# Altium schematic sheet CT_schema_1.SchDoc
size 808 x 528 mm
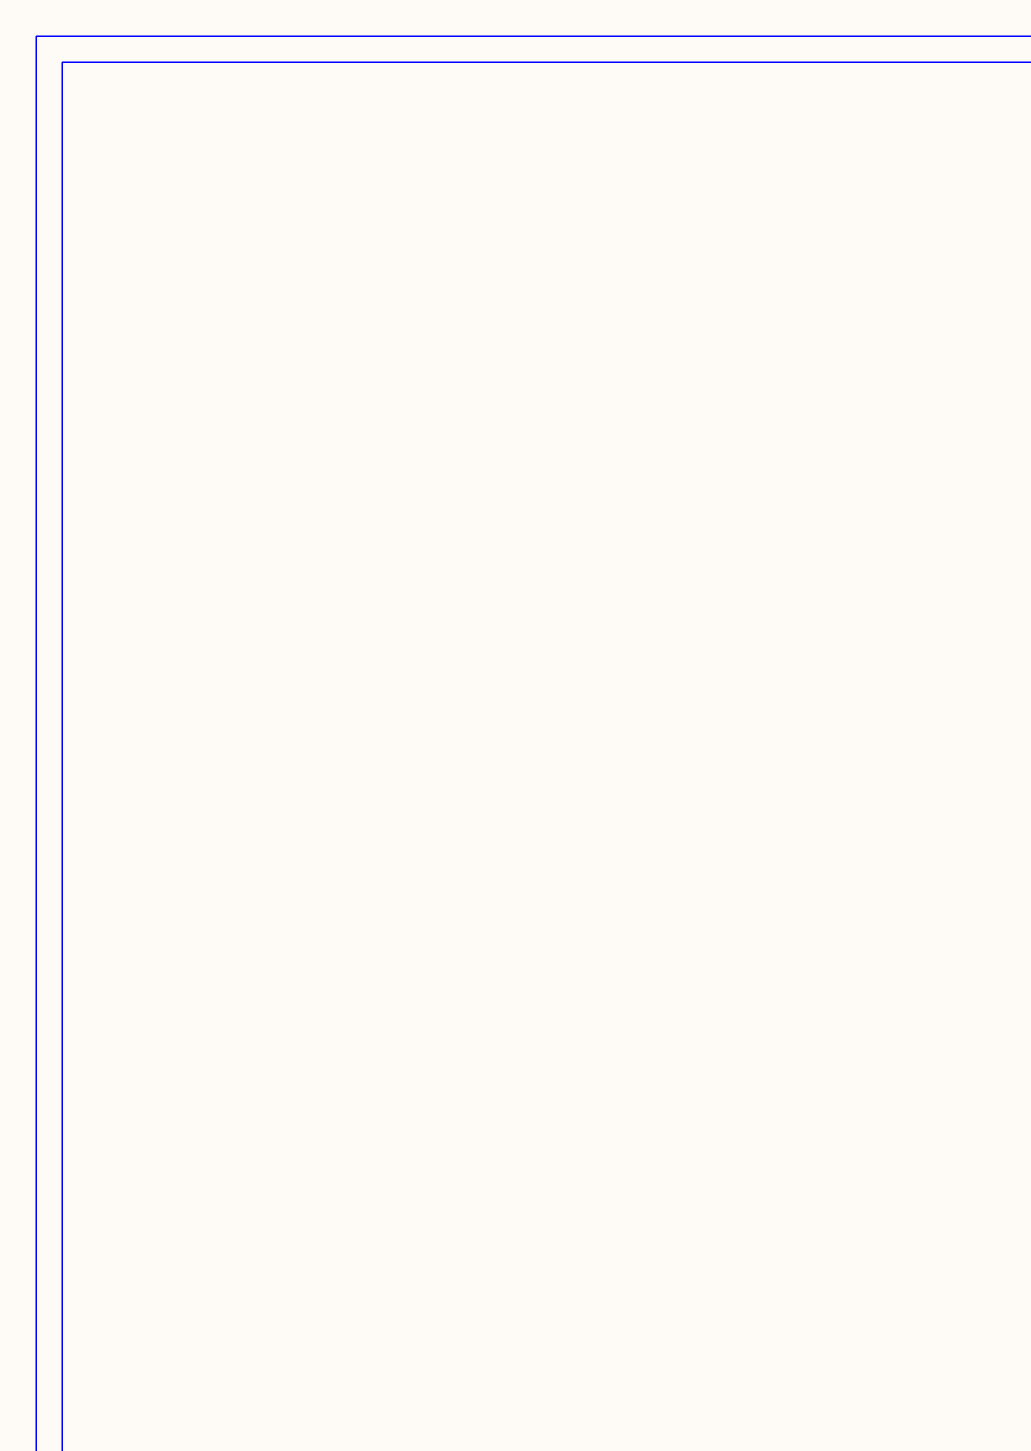
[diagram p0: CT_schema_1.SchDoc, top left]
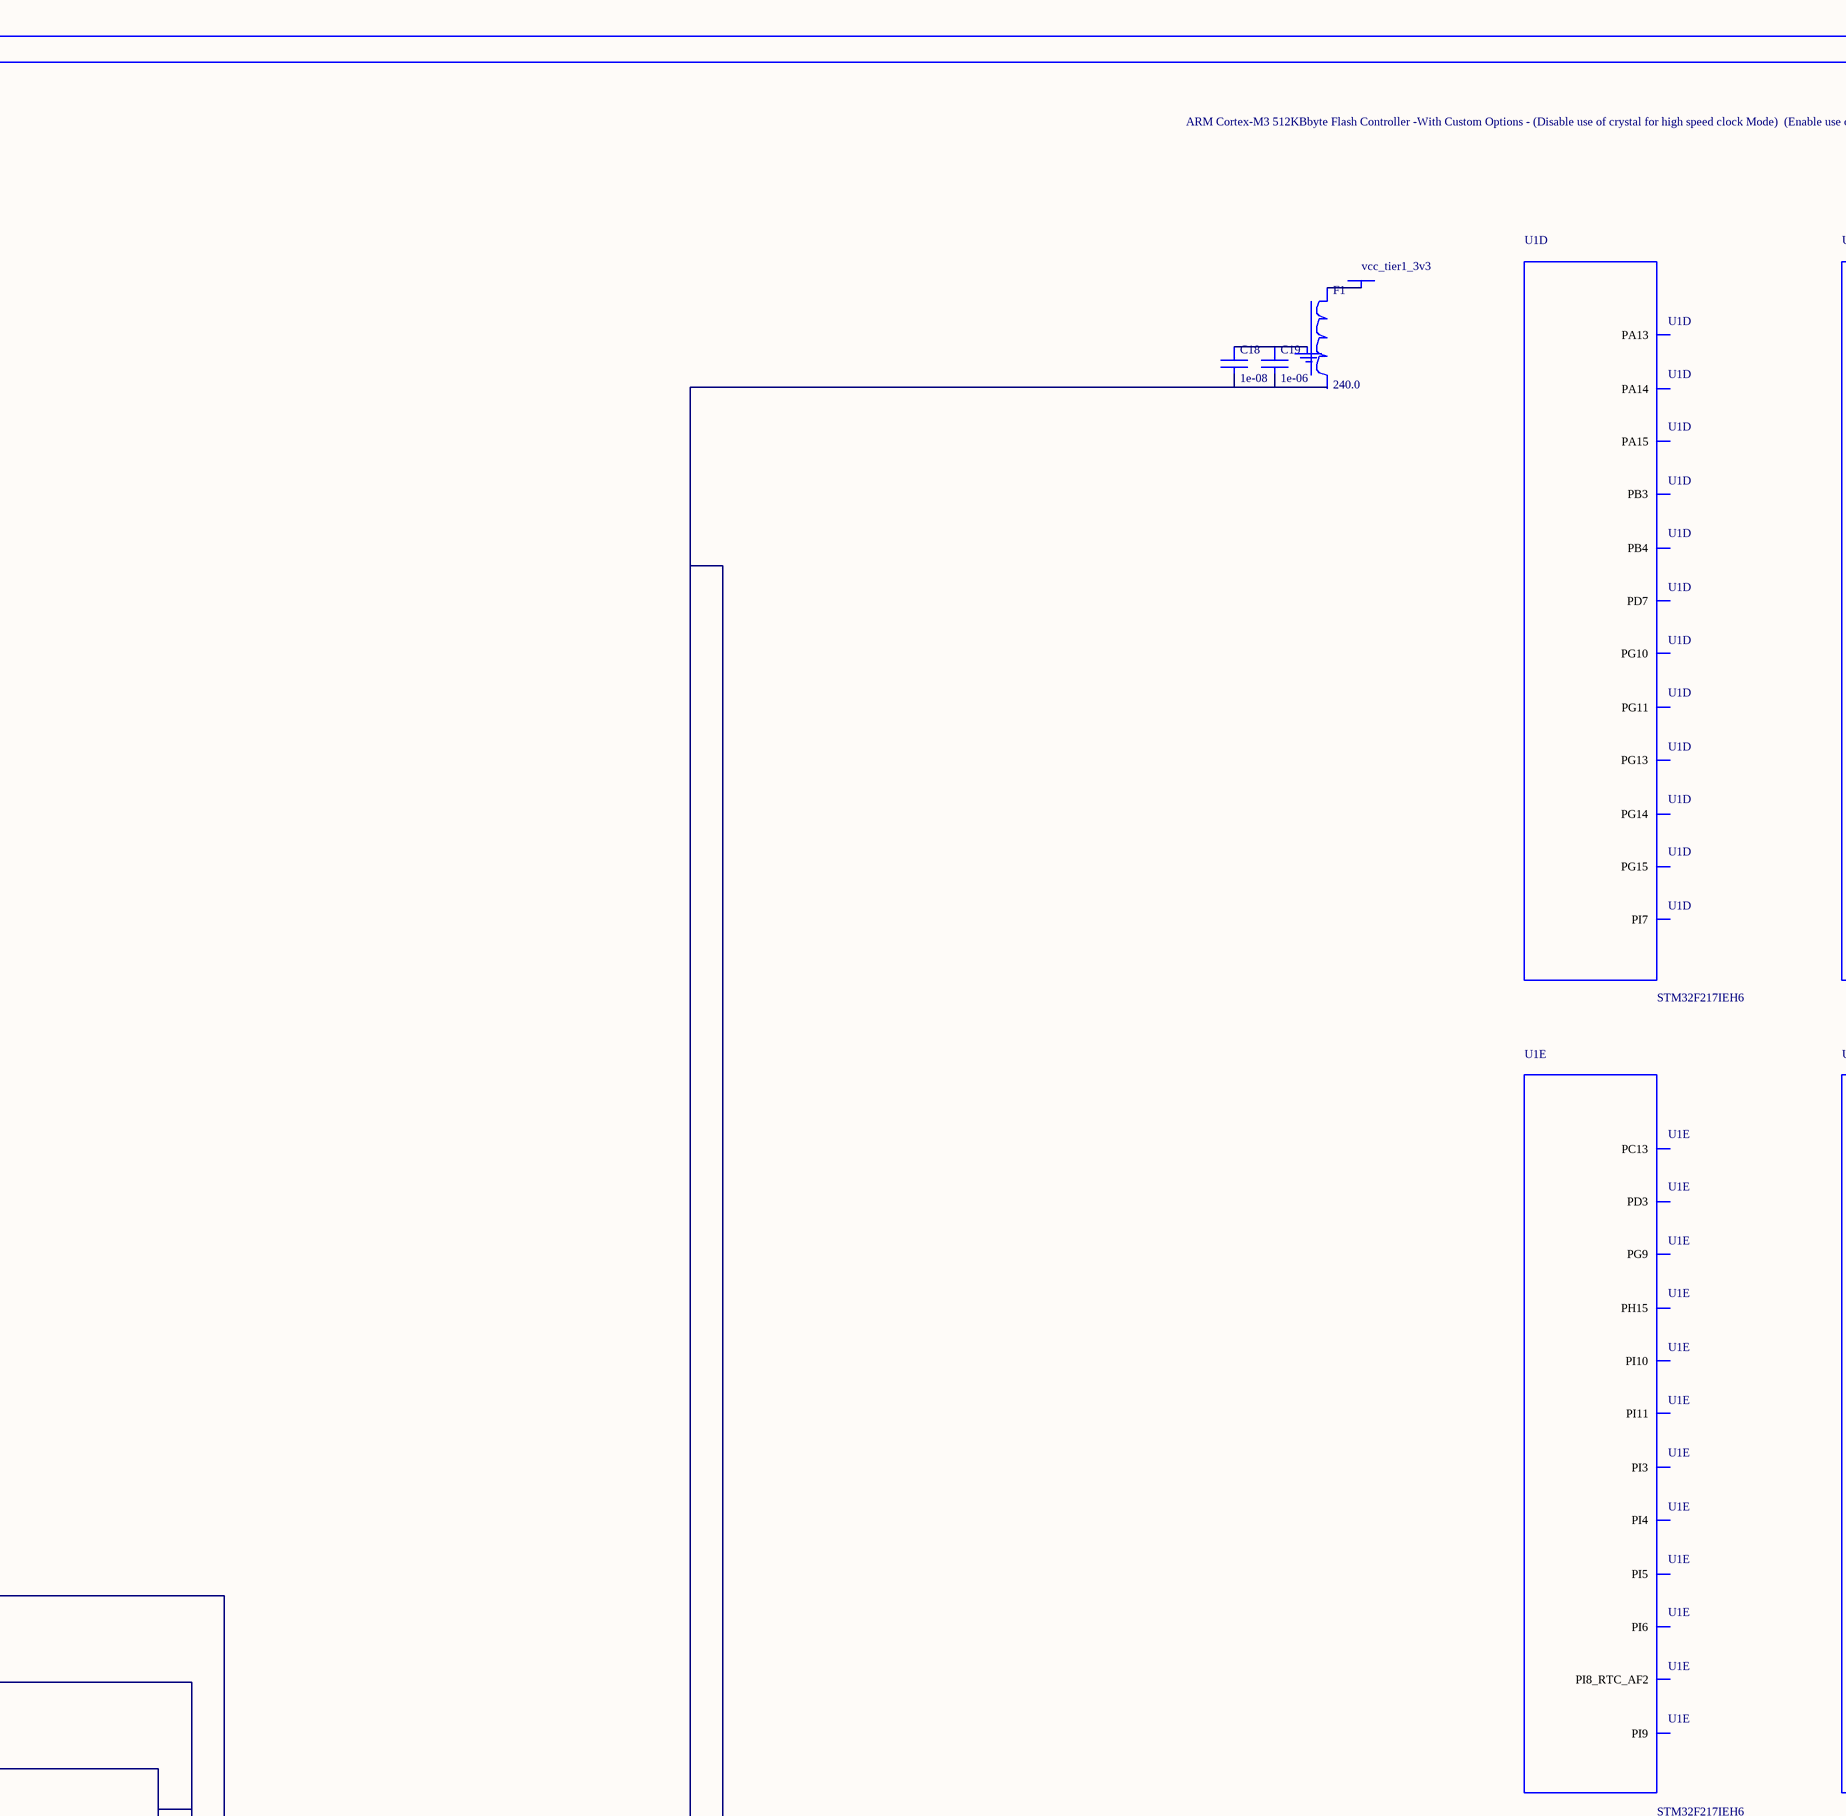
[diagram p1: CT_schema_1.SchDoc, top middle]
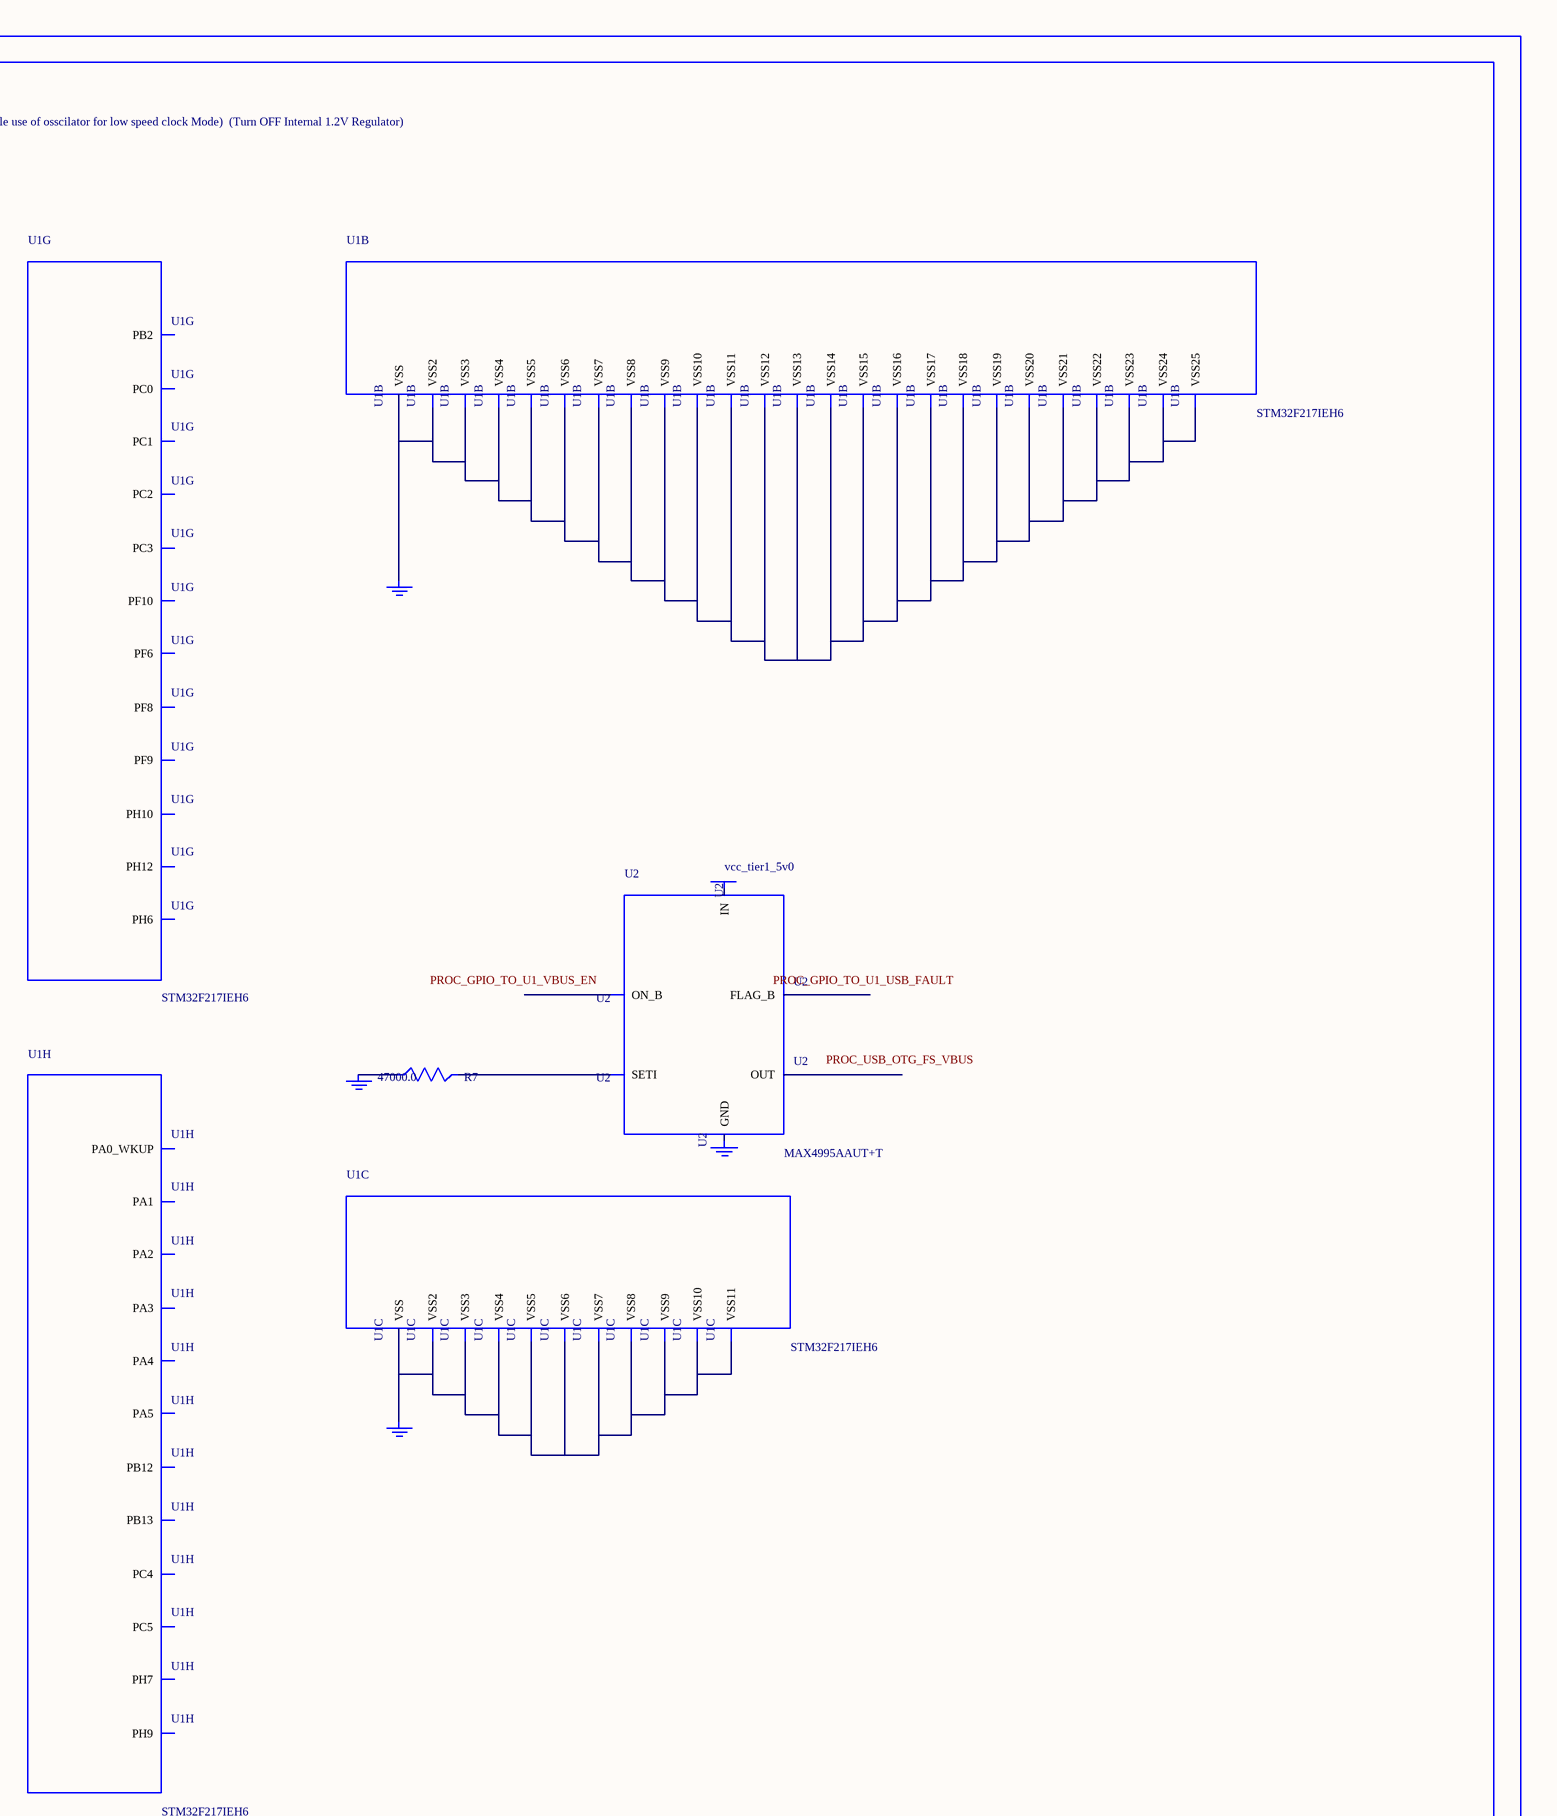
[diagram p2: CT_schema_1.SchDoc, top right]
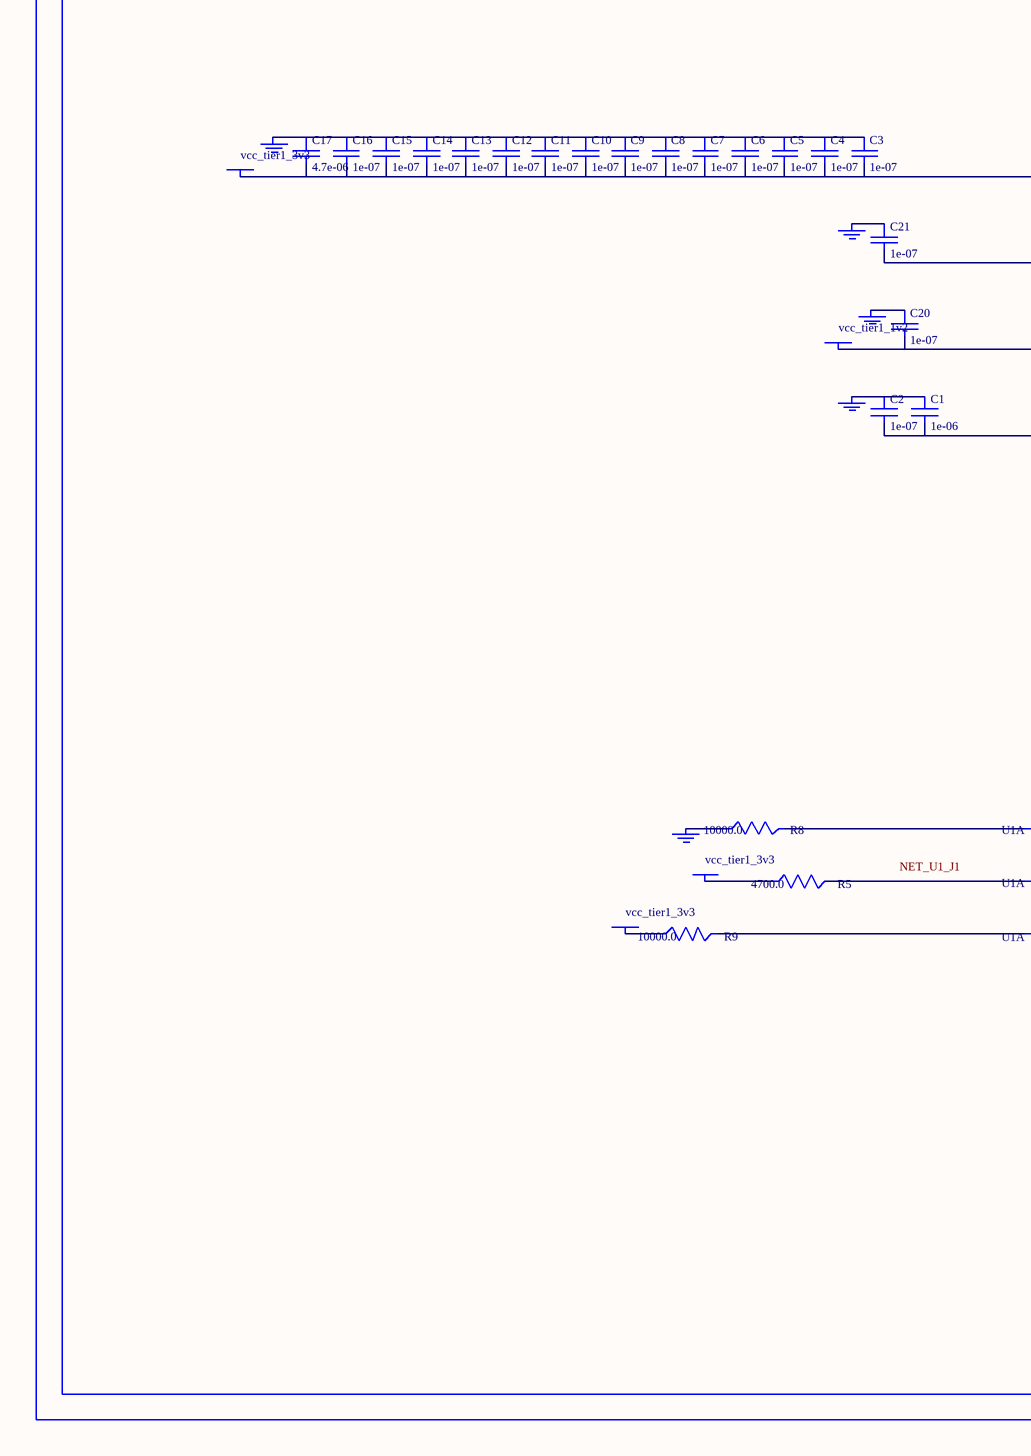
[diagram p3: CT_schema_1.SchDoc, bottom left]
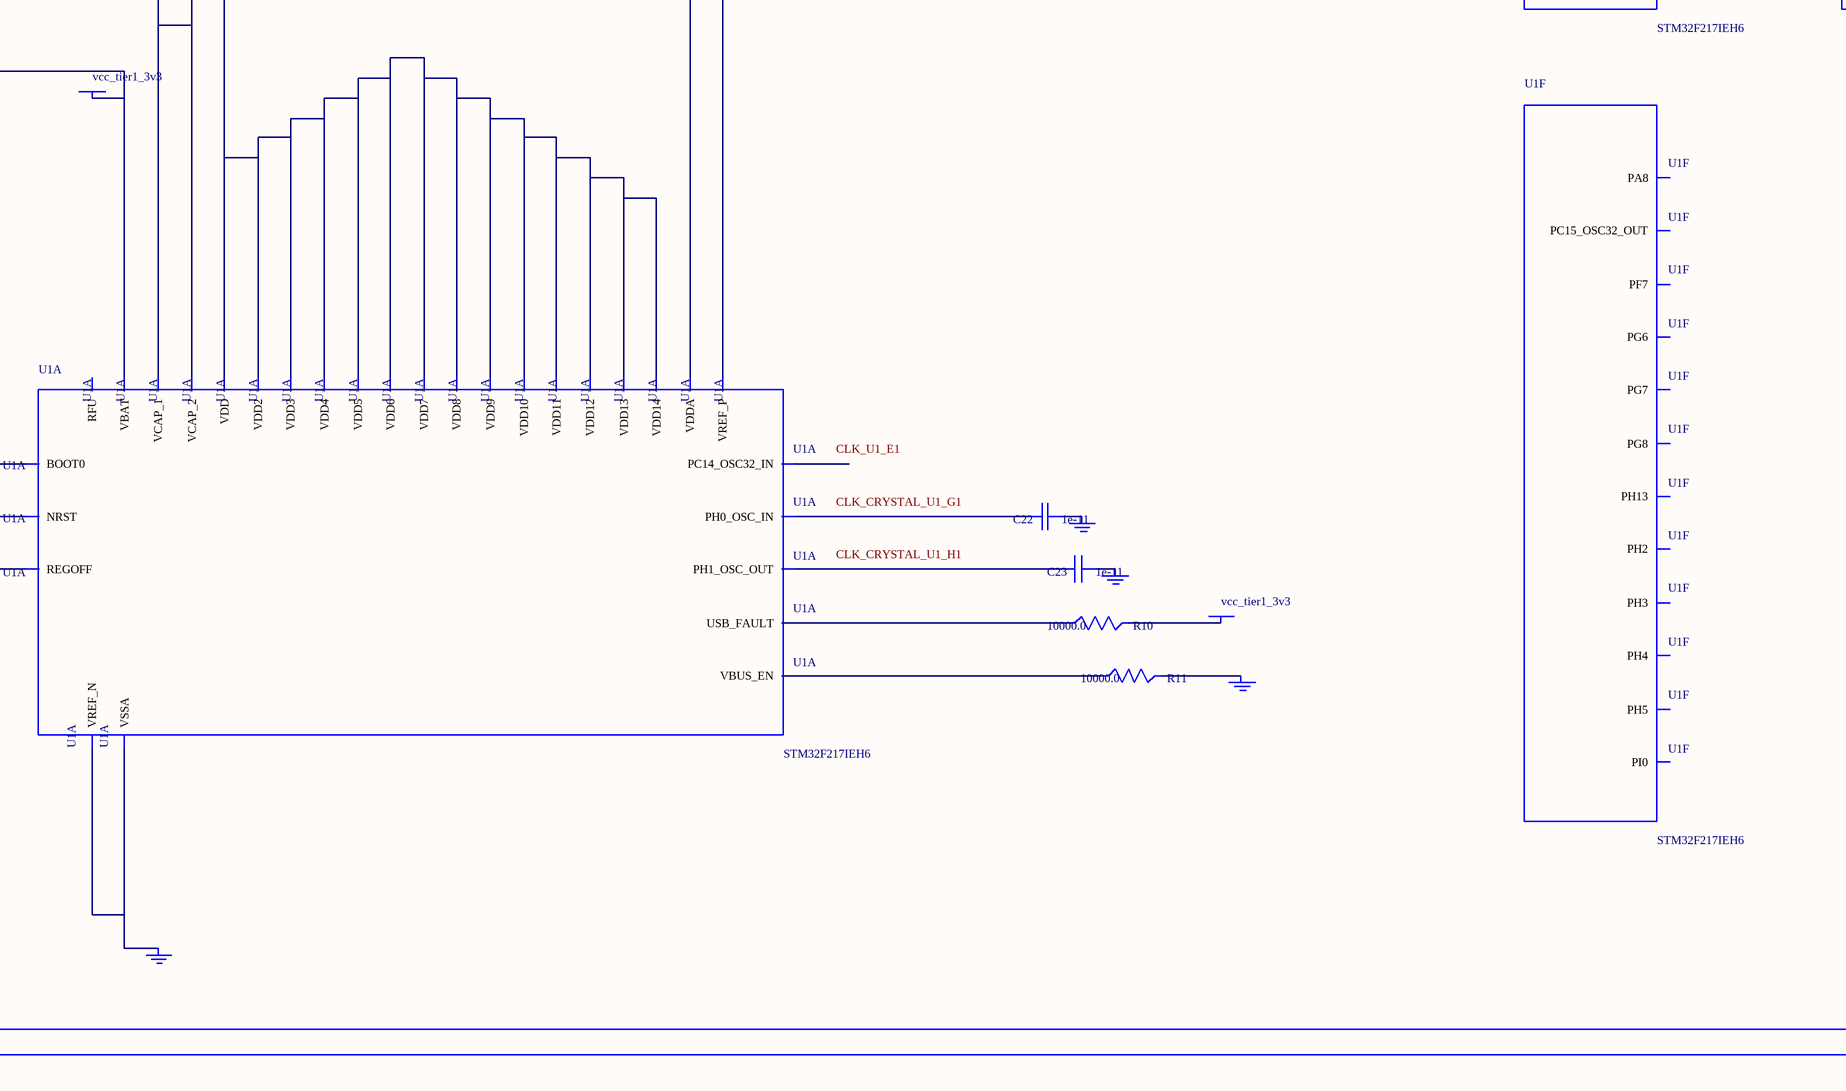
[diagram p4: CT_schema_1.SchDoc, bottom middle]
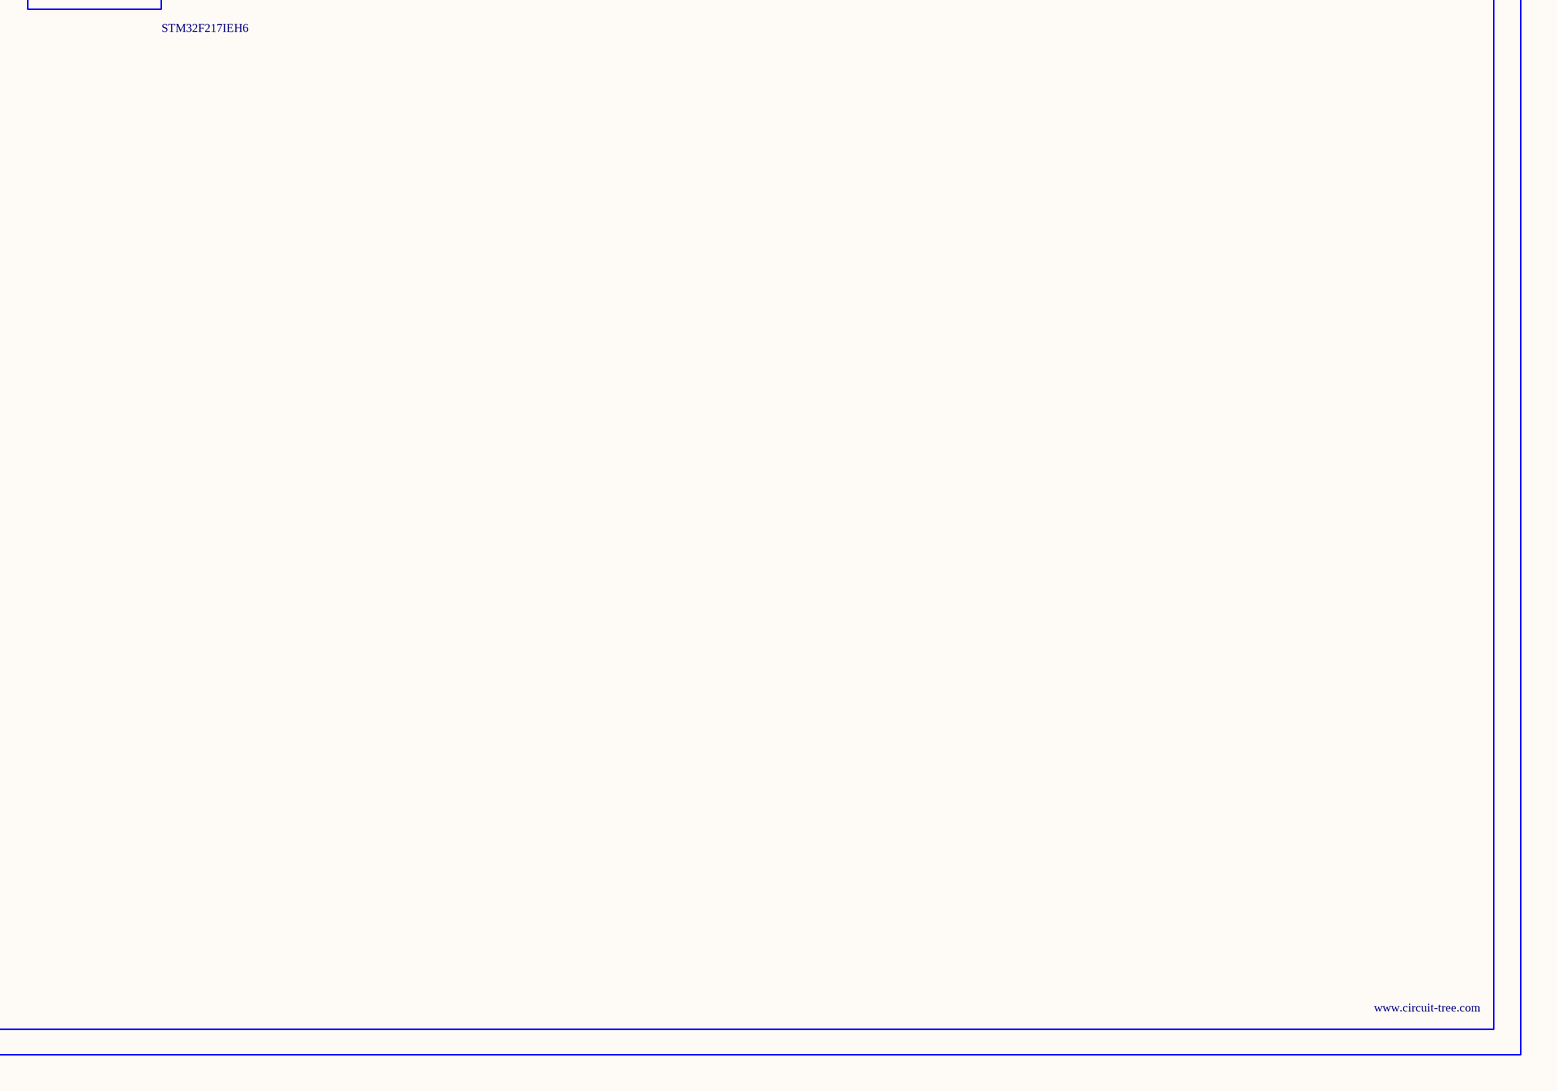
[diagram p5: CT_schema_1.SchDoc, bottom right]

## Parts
BORDER0  (no value)
C1  1e-06  [C0603]
C2  1e-07  [C0603]
C3  1e-07  [C0603]
C4  1e-07  [C0603]
C5  1e-07  [C0603]
C6  1e-07  [C0603]
C7  1e-07  [C0603]
C8  1e-07  [C0603]
C9  1e-07  [C0603]
C10  1e-07  [C0603]
C11  1e-07  [C0603]
C12  1e-07  [C0603]
C13  1e-07  [C0603]
C14  1e-07  [C0603]
C15  1e-07  [C0603]
C16  1e-07  [C0603]
C17  4.7e-06  [C0603]
C18  1e-08  [C0603]
C19  1e-06  [C0603]
C20  1e-07  [C0402]
C21  1e-07  [C0402]
C22  1e-11  [C0402]
C23  1e-11  [C0402]
F1  240.0  [L0603]
GND_INSTANCE_0_0  (no value)
GND_INSTANCE_0_1  (no value)
GND_INSTANCE_0_2  (no value)
GND_INSTANCE_0_3  (no value)
GND_INSTANCE_0_4  (no value)
GND_INSTANCE_0_5  (no value)
GND_INSTANCE_0_6  (no value)
GND_INSTANCE_0_7  (no value)
GND_INSTANCE_0_8  (no value)
GND_INSTANCE_0_9  (no value)
GND_INSTANCE_0_10  (no value)
GND_INSTANCE_0_11  (no value)
GND_INSTANCE_0_12  (no value)
GND_INSTANCE_0_13  (no value)
POWER_INSTANCE_0_0  vcc_tier1_3v3
POWER_INSTANCE_0_1  vcc_tier1_3v3
POWER_INSTANCE_0_2  vcc_tier1_3v3
POWER_INSTANCE_0_3  vcc_tier1_3v3
POWER_INSTANCE_0_4  vcc_tier1_1v2
POWER_INSTANCE_0_5  vcc_tier1_3v3
POWER_INSTANCE_0_6  vcc_tier1_3v3
POWER_INSTANCE_0_7  vcc_tier1_5v0
R5  4700.0  [R0603]
R7  47000.0  [R0603]
R8  10000.0  [R0603]
R9  10000.0  [R0603]
R10  10000.0  [R0603]
R11  10000.0  [R0603]
U1  STM32F217IEH6  [UFBGA176_25]  (parts A,B,C,D,E,F,G,H of 14)
U2  MAX4995AAUT+T  [SOT-23-6]

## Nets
NetC1_1: C1.1 C2.1 GND_INSTANCE_0_0.0(GND)
NetC1_2: C1.2 C2.2 POWER_INSTANCE_0_0.0(PWR) U1.C1(VBAT)
NetC3_1: C3.1 C4.1 C5.1 C6.1 C7.1 C8.1 C9.1 C10.1 C11.1 C12.1 C13.1 C14.1 C15.1 C16.1 C17.1 GND_INSTANCE_0_2.0(GND)
NetC3_2: C3.2 C4.2 C5.2 C6.2 C7.2 C8.2 C9.2 C10.2 C11.2 C12.2 C13.2 C14.2 C15.2 C16.2 C17.2 POWER_INSTANCE_0_2.0(PWR) U1.C5(VDD) U1.C7(VDD2) U1.C8(VDD3) U1.C9(VDD4) U1.F3(VDD5) U1.G3(VDD7) U1.G13(VDD6) U1.H13(VDD8) U1.J12(VDD9) U1.J13(VDD10) U1.K4(VDD11) U1.N8(VDD13) U1.N9(VDD14) U1.N10(VDD12)
NetC18_1: C18.1 C19.1 GND_INSTANCE_0_1.0(GND)
NetC18_2: C18.2 C19.2 U1.P1(VREF_P) U1.R1(VDDA)
NetC20_1: C20.1 GND_INSTANCE_0_4.0(GND)
NetC20_2: C20.2 C21.2 POWER_INSTANCE_0_4.0(PWR) U1.F13(VCAP_2) U1.M10(VCAP_1)
NetC21_1: C21.1 GND_INSTANCE_0_5.0(GND)
NetC22_1: C22.1 GND_INSTANCE_0_6.0(GND)
NetC22_2: C22.2 U1.G1(PH0_OSC_IN)
NetC23_1: C23.1 GND_INSTANCE_0_7.0(GND)
NetC23_2: C23.2 U1.H1(PH1_OSC_OUT)
NetF1_1: F1.1 POWER_INSTANCE_0_1.0(PWR)
NetGND_INSTANCE_0_3_0: GND_INSTANCE_0_3.0(GND) R8.1
NetGND_INSTANCE_0_8_0: GND_INSTANCE_0_8.0(GND) R11.2
NetGND_INSTANCE_0_9_0: GND_INSTANCE_0_9.0(GND) U1.M1(VSSA) U1.N1(VREF_N)
NetGND_INSTANCE_0_10_0: GND_INSTANCE_0_10.0(GND) U1.D5(VSS) U1.D7(VSS2) U1.D8(VSS3) U1.D9(VSS4) U1.F2(VSS7) U1.F6(VSS8) U1.F7(VSS9) U1.F8(VSS10) U1.F9(VSS11) U1.F10(VSS5) U1.F12(VSS6) U1.G2(VSS14) U1.G6(VSS15) U1.G7(VSS16) U1.G8(VSS17) U1.G9(VSS18) U1.G10(VSS12) U1.G12(VSS13) U1.H6(VSS21) U1.H7(VSS22) U1.H8(VSS23) U1.H9(VSS24) U1.H10(VSS19) U1.H12(VSS20) U1.J10(VSS25)
NetGND_INSTANCE_0_11_0: GND_INSTANCE_0_11.0(GND) U1.J6(VSS) U1.J7(VSS2) U1.J8(VSS3) U1.J9(VSS4) U1.K6(VSS6) U1.K7(VSS7) U1.K8(VSS8) U1.K9(VSS9) U1.K10(VSS5) U1.M8(VSS10) U1.M9(VSS11)
NetGND_INSTANCE_0_12_0: GND_INSTANCE_0_12.0(GND) R7.1
NetPOWER_INSTANCE_0_3_0: POWER_INSTANCE_0_3.0(PWR) R9.1
NetPOWER_INSTANCE_0_5_0: POWER_INSTANCE_0_5.0(PWR) R10.2
NetPOWER_INSTANCE_0_6_0: POWER_INSTANCE_0_6.0(PWR) R5.1
NetR5_2: R5.2 U1.J1(NRST)
NetR7_2: R7.2 U2.3(SETI)
NetR8_2: R8.2 U1.D6(BOOT0)
NetR9_2: R9.2 U1.L4(REGOFF)
NetR10_1: R10.1 U1.A6(USB_FAULT)
NetR11_1: R11.1 U1.A2(VBUS_EN)

Not connected (* = marked no-connect by the designer): F1 2; GND_INSTANCE_0_13 0(GND); POWER_INSTANCE_0_7 0(PWR); U1 A7(PG14) A8(PG13) A9(PB4) A10(PB3) A11(PD7) A13(PA15) A14(PA14) A15(PA13) B7(PG15) B9(PG11) B10(PG10) C2(PI7) C3(PI6) C4(PI5) C6(RFU) C10(PG9) C13(PI3) D1(PC13) D2(PI8_RTC_AF2) D3(PI9) D4(PI4) D11(PD3) D13(PH15) E1(PC14_OSC32_IN) E3(PI10) E4(PI11) E12(PH13) E14(PI0) F1(PC15_OSC32_OUT) F4(PH2) F15(PA8) G4(PH3) H4(PH4) H14(PG8) J4(PH5) J14(PG7) J15(PG6) K1(PF7) K2(PF6) K12(PH12) L1(PF10) L2(PF9) L3(PF8) L13(PH10) M2(PC0) M3(PC1) M4(PC2) M5(PC3) M6(PB2) M11(PH6) M13(PH9) N2(PA1) N3(PA0_WKUP) N4(PA4) N5(PC4) N12(PH7) P2(PA2) P4(PA5) P5(PC5) P12(PB12) P13(PB13) R2(PA3); U2 1(OUT) 2(GND) 4(ON_B) 5(IN) 6(FLAG_B)

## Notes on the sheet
- Labels drawn without touching a wire or pin: CLK_CRYSTAL_U1_G1, CLK_CRYSTAL_U1_H1, CLK_U1_E1, NET_U1_J1, PROC_GPIO_TO_U1_USB_FAULT, PROC_GPIO_TO_U1_VBUS_EN, PROC_USB_OTG_FS_VBUS

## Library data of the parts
BORDER0 = BORDER_PAGE0
C1 C19 = C0603C105K3RACTU
C2-C16 = 06035C104K4Z2A
C17 = GRM188R6YA475KE15D
C18 = 06035C103K4Z2A
C20 C21 = C0402C104K3RACTU
C22 C23 = C0402C100K3GACTU
F1 = Z0603C241ASMST
GND_INSTANCE_0_0-GND_INSTANCE_0_13 = GND
POWER_INSTANCE_0_0-POWER_INSTANCE_0_7 = PWR
R5 = RC0603JR-074K7L
R7 = RC0603JR-0747KL
R8-R11 = RC0603JR-0710KL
